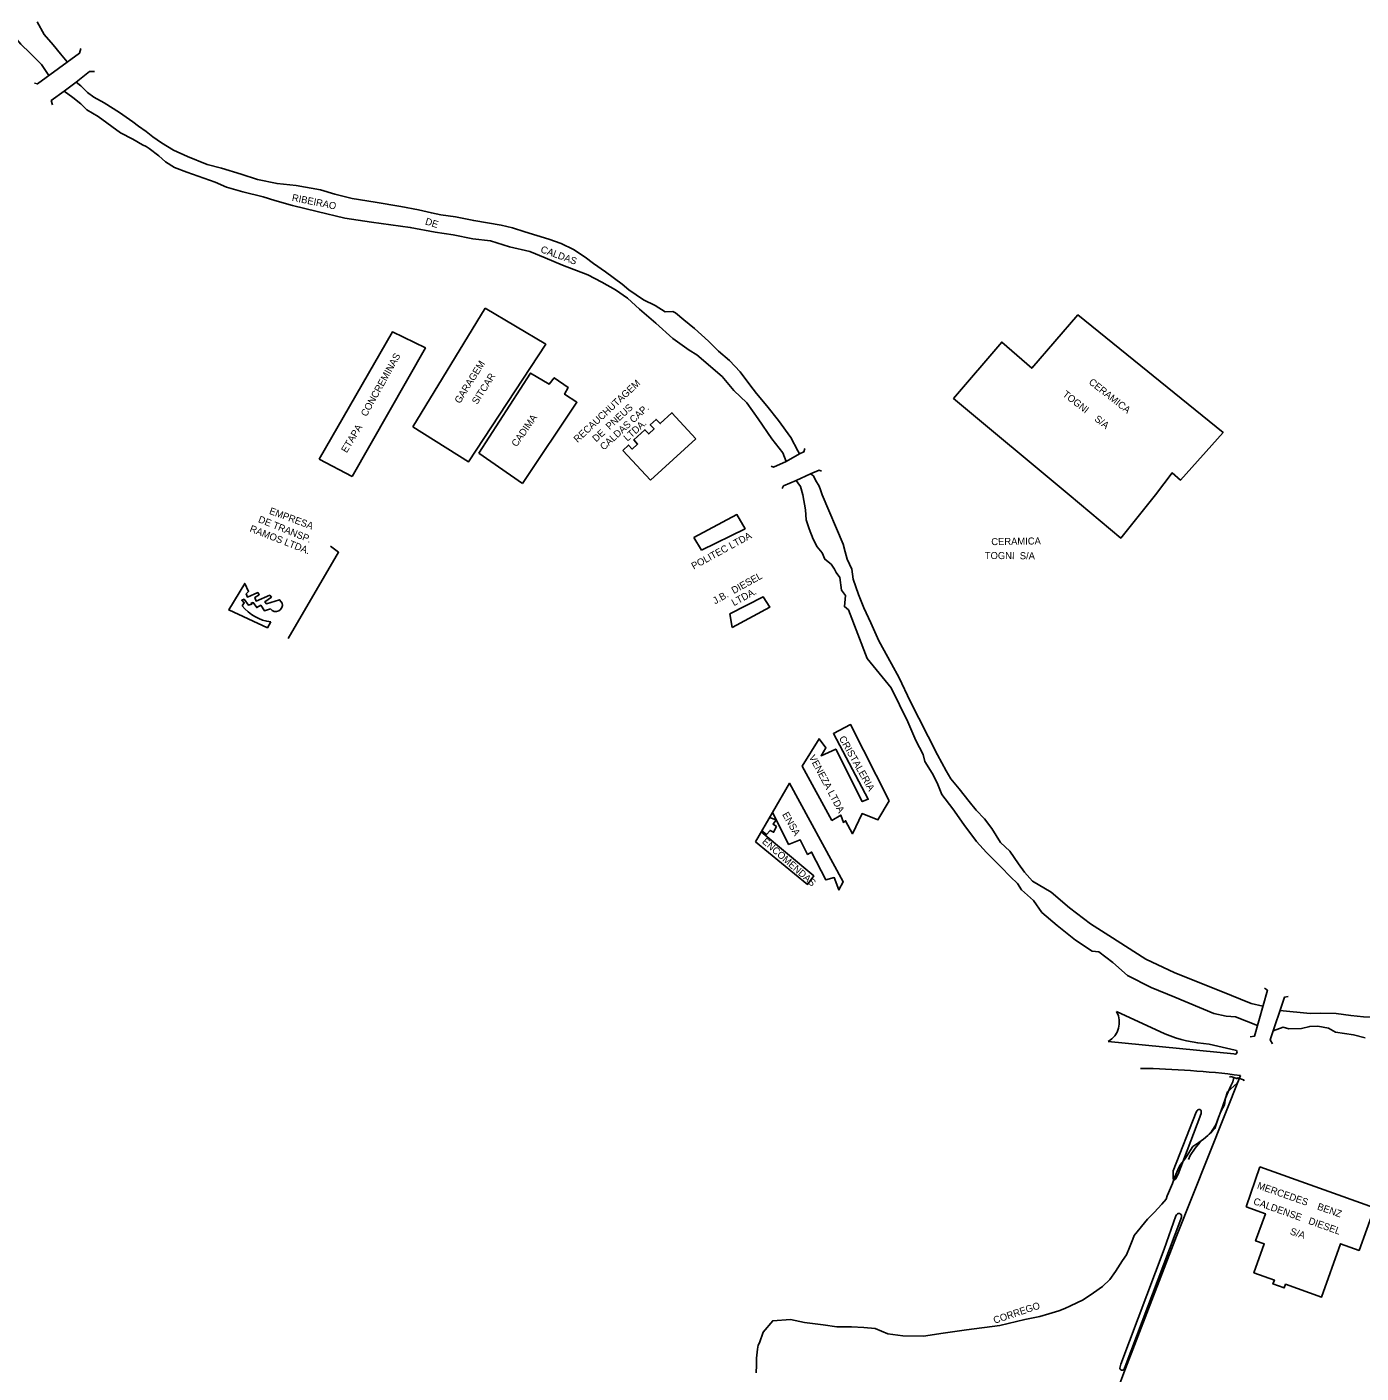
# Model space of a CAD drawing. Extents: x 325899 to 363134, y 7578590 to 7592502.
# Drawn here: x 334413 to 335173, y 7590002 to 7590768 of the extents above; entities that cross this region are included whole.
import ezdxf

# ---------------------------------------------------------------- set-up
doc = ezdxf.new("R2010")
doc.units = 0
for name, color, linetype in [('EDIFEXISTENT', 7, 'Continuous'), ('EDIFIDENTIF', 7, 'Continuous'), ('EDIFOBRAEXIS', 7, 'Continuous')]:
    doc.layers.add(name, color=color, linetype=linetype)

msp = doc.modelspace()

# ---------------------------------------------------------------- linework, layer by layer
at = {"layer": 'EDIFEXISTENT'}
for points in [[(334417.87, 7590736.5), (334419.49, 7590736.06), (334443.51, 7590753.51), (334444.25, 7590756.28)], [(334427.99, 7590724.19), (334427.33, 7590726.62), (334434.69, 7590731.93), (334441.52, 7590737.06), (334449.2, 7590743.16), (334451.89, 7590743.16)], [(334674.6, 7590608.27), (334709.05, 7590587.76), (334665.07, 7590520.77), (334633.23, 7590540.67)], [(334633.23, 7590540.67), (334674.6, 7590608.27)], [(335007.21, 7590501.91), (334941.33, 7590556.89), (334968.82, 7590588.94), (334985.9, 7590574.03), (335012.18, 7590604.43), (335094.84, 7590537.54), (335070.57, 7590510.36), (335065.86, 7590514.42), (335056.42, 7590501.91)], [(334580, 7590522.34), (334621.71, 7590594.78), (334640.48, 7590585.63), (334598.78, 7590512.32)], [(334670.91, 7590525.66), (334700.4, 7590571.33), (334710.89, 7590564.98), (334713.84, 7590568.61), (334721.87, 7590563.07), (334719.8, 7590559.24), (334726.75, 7590554.72), (334695.77, 7590508.37)], [(334752.89, 7590527.28), (334756.11, 7590530.35), (334758.25, 7590527.99), (334761.36, 7590530.84), (334759.18, 7590533.21), (334765.55, 7590539.01), (334767.7, 7590536.65), (334770.78, 7590539.51), (334768.56, 7590541.87), (334771.91, 7590544.94), (334774.21, 7590542.58), (334780.87, 7590548.74), (334794.45, 7590533.92)], [(334794.45, 7590533.92), (334768.78, 7590510.25)], [(334598.78, 7590512.32), (334580, 7590522.34)], [(334695.77, 7590508.37), (334670.91, 7590525.66)], [(334768.78, 7590510.25), (334752.89, 7590527.28)], [(334837.4, 7590518.24), (334838.82, 7590517.66), (334845.95, 7590520.88), (334853.59, 7590525.36), (334856.13, 7590526.47), (334856.66, 7590528.37)], [(334843.76, 7590505.48), (334844.52, 7590507.03), (334851.73, 7590510.12), (334859.87, 7590513.96), (334864.69, 7590516.07), (334866.19, 7590515.48)], [(335007.21, 7590501.91), (335036.61, 7590477.29), (335056.42, 7590501.91)], [(334793.37, 7590477.64), (334817.9, 7590490.76), (334822.54, 7590482.64), (334797.74, 7590470.52)], [(334797.74, 7590470.52), (334793.37, 7590477.64)], [(334813.94, 7590434.15), (334832.82, 7590443.95), (334836.66, 7590437.9), (334815.28, 7590426.44)], [(334815.28, 7590426.44), (334813.94, 7590434.15)], [(334872.02, 7590316.44), (334855.1, 7590347.46), (334864.73, 7590363.08), (334868.64, 7590357.81), (334865.88, 7590353.36), (334874.21, 7590357.11), (334889.33, 7590327.22), (334892.71, 7590328.61), (334872.86, 7590365.97), (334882.71, 7590371.12), (334904.65, 7590327.75)], [(334828.48, 7590304.36), (334847.84, 7590337.71), (334878.53, 7590281.63), (334876.02, 7590276.95), (334873.34, 7590284), (334868.67, 7590282.61), (334860.43, 7590298.51), (334858.16, 7590297.18), (334853.98, 7590305.41), (334847.39, 7590302.81), (334838.28, 7590321.24)], [(334904.65, 7590327.75), (334898.23, 7590316.79), (334889.24, 7590320.43), (334883.77, 7590308.89), (334879.82, 7590316.34), (334878.64, 7590315.35), (334877.09, 7590319.54), (334872.02, 7590316.44)], [(334836.54, 7590318.24), (334840.2, 7590316.84), (334838.52, 7590314.3), (334840.41, 7590313.05), (334838.86, 7590309.77), (334836.85, 7590310.79), (334834.76, 7590308.45), (334832.11, 7590310.61)], [(334831.81, 7590310.09), (334861.71, 7590284.89), (334858.22, 7590280.11), (334828.48, 7590304.36)], [(335118.44, 7590221), (335120.12, 7590219.77), (335112.81, 7590193.66), (335110.23, 7590193.19)], [(335131.94, 7590216.2), (335129.77, 7590215.81), (335121.67, 7590191.61), (335123.02, 7590189.29)], [(335098.52, 7590170.3), (335099.33, 7590170.68), (335102.72, 7590169.59), (335102.98, 7590169.08)], [(335102.38, 7590169.44), (335103.19, 7590169.83), (335106.57, 7590168.73), (335106.83, 7590168.23)], [(335066.46, 7590116.91), (335079.57, 7590150.35), (335079.9, 7590151.01), (335080.1, 7590151.39), (335080.48, 7590151.69), (335081.07, 7590151.89), (335081.65, 7590151.81), (335082.14, 7590151.53), (335082.42, 7590151.04), (335082.47, 7590150.28), (335082.31, 7590149.53), (335081.99, 7590148.58), (335081.58, 7590147.49), (335069.31, 7590115), (335068.17, 7590112.86), (335067.95, 7590112.43), (335067.72, 7590112.11), (335067.37, 7590111.79), (335067.19, 7590111.74), (335066.99, 7590111.76), (335066.66, 7590111.91), (335066.48, 7590112.17), (335066.4, 7590112.42), (335066.37, 7590112.78), (335066.46, 7590116.91)], [(335115.75, 7590119.18), (335181.05, 7590095.82), (335172.38, 7590071.59), (335161.85, 7590075.36), (335150.99, 7590045.02), (335130.47, 7590052.36), (335129.71, 7590050.24), (335123.3, 7590052.54), (335124.08, 7590054.72), (335112.44, 7590058.89), (335118.31, 7590075.28), (335113.43, 7590077.03), (335118.95, 7590092.45), (335107.98, 7590096.37)], [(335107.98, 7590096.37), (335115.75, 7590119.18)]]:
    msp.add_lwpolyline(points, dxfattribs=at)
at = {"layer": 'EDIFOBRAEXIS'}
for points in [[(334399.02, 7590772.12), (334401.6, 7590767.32), (334406.59, 7590762.65), (334409.99, 7590758.75), (334415.36, 7590753.62), (334421.71, 7590747.01), (334425.94, 7590740.73), (334425.94, 7590740.73)], [(334419.27, 7590771.33), (334423.33, 7590764.21), (334428.38, 7590758.22), (334432.51, 7590753.16), (334436.48, 7590748.58)], [(334441.52, 7590737.06), (334444.23, 7590734.93), (334448.06, 7590731.18), (334451.66, 7590728.47), (334457.44, 7590725.33), (334466.22, 7590719.8), (334473.79, 7590714.36), (334476.99, 7590711.97), (334481.39, 7590708.84)], [(334434.69, 7590731.93), (334439.69, 7590728.24), (334444.14, 7590724.68), (334447.67, 7590721.21), (334454.06, 7590717.51), (334466.73, 7590708.14), (334473.75, 7590704.49), (334479.23, 7590701.32), (334481.39, 7590700.4)], [(334481.39, 7590708.84), (334485.11, 7590705.88), (334490.11, 7590702.43), (334497.03, 7590698.34), (334504.86, 7590694.7), (334516.22, 7590690.03), (334524.23, 7590688.09), (334535.54, 7590684.56), (334544.82, 7590681.51), (334555.95, 7590679.21), (334566.78, 7590678.19), (334580.68, 7590675.64), (334588.97, 7590673.28), (334598.81, 7590670.78), (334611.8, 7590668.67), (334626.43, 7590666.22), (334636.47, 7590664.33), (334643.85, 7590662.58), (334649.35, 7590661.51), (334657.7, 7590660.23), (334667.99, 7590658.19), (334683.72, 7590655.49), (334690.13, 7590654.01), (334697.03, 7590651.68), (334710.85, 7590647.55), (334717.72, 7590645.04), (334724.87, 7590641.71), (334731.41, 7590637.39), (334736.28, 7590633.76), (334743.04, 7590629.04), (334752.52, 7590621.88), (334756.38, 7590618.8), (334764.79, 7590612.99), (334771.33, 7590609.74), (334777.01, 7590606.13), (334781.37, 7590606.41), (334782.92, 7590605.72), (334787.61, 7590601.71), (334793.69, 7590596.78), (334801.73, 7590589.5), (334807.43, 7590583.71), (334813.76, 7590578.43), (334819.8, 7590572.11), (334825.37, 7590564.57), (334829.12, 7590559.62), (334835.02, 7590552.61), (334841.66, 7590544.29), (334848.7, 7590534.54), (334852.55, 7590527.01), (334853.59, 7590525.36)], [(334481.39, 7590700.4), (334483.04, 7590699.18), (334488.62, 7590694.96), (334492.43, 7590691.72), (334497.6, 7590688.34), (334504.57, 7590685.83), (334520.7, 7590680.06), (334527.17, 7590677.23), (334536.42, 7590674.59), (334548.01, 7590671.74), (334554.75, 7590669.63), (334564.77, 7590666.83), (334578.84, 7590663.39), (334594.62, 7590659.55), (334609.78, 7590657.3), (334631.87, 7590654.24), (334645.95, 7590651.64), (334656.37, 7590650.04), (334667.5, 7590647.87), (334677.47, 7590646.72), (334688.37, 7590643.21), (334699.99, 7590640.56), (334708.66, 7590636.98), (334718.62, 7590632.74), (334732.92, 7590627.25), (334740.98, 7590623.03), (334748.74, 7590618.71), (334755.61, 7590613.99), (334762.45, 7590607.79), (334771.68, 7590599.72), (334781.51, 7590591.09), (334790.64, 7590584.43), (334795.12, 7590581.79), (334809.55, 7590569.33), (334816.18, 7590561.36), (334823.64, 7590554.4), (334830.04, 7590545.16), (334837.9, 7590533.79), (334844.13, 7590525.98), (334845.95, 7590520.88)], [(334859.87, 7590513.96), (334861.47, 7590512.82), (334862.94, 7590509.98), (334864.56, 7590507.32), (334865.27, 7590505.46), (334866.58, 7590501.91)], [(334851.73, 7590510.12), (334852.71, 7590508.77), (334854.07, 7590506.63), (334855.52, 7590501.91)], [(335114.51, 7590199.74), (335101.9, 7590204.73), (335096.55, 7590205.08), (335089.53, 7590206.58), (335067.46, 7590215.91), (335053.97, 7590221.32), (335040.5, 7590228.27), (335032.02, 7590235.61), (335024.08, 7590241.72), (335020.33, 7590242.02), (335010.79, 7590248.34), (335000.42, 7590256.71), (334991.71, 7590264.15), (334986.83, 7590270.98), (334980.1, 7590276.94), (334977.78, 7590280.58), (334973.72, 7590284.3), (334968.24, 7590290.01), (334960.06, 7590298.32), (334954.39, 7590304.56), (334947.14, 7590314.24), (334940.9, 7590323.14), (334934.67, 7590331.29), (334931.94, 7590337.93), (334929.06, 7590343.46), (334925.02, 7590350.09), (334924.11, 7590354.09), (334919.83, 7590362.09), (334915.27, 7590372.75), (334905.73, 7590392.01), (334892.13, 7590408.7), (334881.4, 7590436.44), (334879.14, 7590438.36), (334879.76, 7590444.54), (334877.43, 7590447.58), (334876.62, 7590454.85), (334874.52, 7590457.72), (334873.5, 7590459.72), (334871.63, 7590462.46), (334867.99, 7590465.25), (334866.42, 7590468.89), (334863.64, 7590472.34), (334861.43, 7590476.63), (334859.01, 7590482.52), (334857.46, 7590487.78), (334857.02, 7590493.5), (334855.52, 7590501.91)], [(334866.58, 7590501.91), (334878.4, 7590473.83), (334879.54, 7590469.56), (334880.71, 7590465.28), (334883.38, 7590459.63), (334884.2, 7590453.91), (334887.14, 7590445.14), (334890.18, 7590437.69), (334894.21, 7590429.15), (334898.74, 7590418.9), (334906.04, 7590405.77), (334910.32, 7590397.74), (334916.67, 7590384.36), (334921.54, 7590374.77), (334932.11, 7590353.81), (334937.04, 7590344.7), (334939.75, 7590340.18), (334944.6, 7590334.57), (334950.17, 7590327.21), (334954.15, 7590322.45), (334958.99, 7590317.51), (334963.08, 7590311.92), (334968.1, 7590303.87), (334973.35, 7590299.06), (334978.36, 7590291.88), (334981.68, 7590287.01), (334986.4, 7590281.85), (334996.86, 7590275.56), (335007.35, 7590266.71), (335019.31, 7590257.57), (335029.77, 7590250.9), (335050.8, 7590237.51), (335067.37, 7590229.76), (335093.65, 7590219.22), (335110.94, 7590212.21), (335117.61, 7590210.8)], [(334586.32, 7590472.67), (334591.01, 7590469.28), (334562.22, 7590420.07)], [(334552.46, 7590429.55), (334550.43, 7590426.27), (334528.41, 7590436.38), (334537.53, 7590451.49), (334539.76, 7590446.94), (334538.4, 7590445.54), (334539.1, 7590443.69), (334545.01, 7590446.27), (334545.8, 7590445.03), (334543.23, 7590443.44), (334543.98, 7590441.47), (334551.76, 7590444.76), (334552.78, 7590443.68), (334549.07, 7590441.1), (334550.02, 7590439.86), (334557.4, 7590442.22), (334558.85, 7590440.25)], [(334552.24, 7590437.02), (334548.88, 7590435.88), (334546.63, 7590439.06), (334544.36, 7590437.7), (334542.36, 7590440.63), (334541.3, 7590440.34), (334541.53, 7590439.68), (334539.64, 7590439.16), (334537.21, 7590442.49), (334535.82, 7590441.9), (334537.32, 7590440.39), (334536.04, 7590438.79)], [(335034.25, 7590207.61), (335061.74, 7590195)], [(335127.24, 7590208.26), (335144.39, 7590206.53), (335150.16, 7590206.82), (335159.36, 7590206.58), (335167.65, 7590205.44), (335174.8, 7590204.62), (335180.88, 7590204.46), (335185.95, 7590203.35), (335196.77, 7590203.09), (335199.54, 7590203.47), (335202.54, 7590203.18), (335212.7, 7590200.21), (335216.52, 7590199.9), (335229.19, 7590198.82), (335236.87, 7590198.04), (335241.05, 7590198.06), (335246.57, 7590198.38), (335262.75, 7590196.5), (335270.48, 7590195.36), (335273.49, 7590195.64), (335281.39, 7590195.43)], [(335123.34, 7590196.62), (335129.17, 7590198.73), (335132.26, 7590197.86), (335139.58, 7590198.04), (335144.29, 7590199.16), (335148.79, 7590199.36), (335154.98, 7590198.16), (335158.82, 7590195.86), (335169.14, 7590194.38), (335175.79, 7590192.67)], [(335101.02, 7590183.58), (335029.42, 7590190.59)], [(335086.93, 7590189.11), (335101.85, 7590185.69)], [(335103.98, 7590169.57), (335103.58, 7590168.41), (335102.95, 7590166.85), (335097.42, 7590161.86), (335096.25, 7590158.3), (335095.67, 7590154.48), (335093.56, 7590150.66), (335092.21, 7590147.24), (335090.16, 7590141), (335088.55, 7590139.24), (335087.04, 7590137.83), (335083.67, 7590134.96), (335081.02, 7590133.04), (335077.71, 7590130.76), (335074.06, 7590125.14), (335072.88, 7590123.48), (335070.28, 7590119.98), (335069.03, 7590117.41), (335067.4, 7590113.49), (335066.06, 7590109.67), (335063.8, 7590104.44), (335063, 7590102.61), (335062.53, 7590100.7), (335059.93, 7590097.99), (335055.67, 7590093.21), (335051.91, 7590089.47), (335044.2, 7590080.07), (335043.5, 7590078.01), (335041.47, 7590073.19), (335039.8, 7590069.06), (335037.61, 7590065.77), (335033.66, 7590059.62), (335030.29, 7590055), (335026.1, 7590051.03), (335021.11, 7590047.42), (335015.22, 7590043.52), (335008, 7590040.04), (335004.81, 7590038.59), (335001.36, 7590037.27), (334995.68, 7590035.53), (334990.41, 7590034), (334981.91, 7590032.24), (334967.67, 7590028.84), (334948.63, 7590026.33), (334935.46, 7590024.39), (334924.19, 7590022.79), (334912.5, 7590022.94), (334903.93, 7590024.05), (334896.59, 7590027.2), (334890.31, 7590027.67), (334883.22, 7590028), (334874.83, 7590028.02), (334867.02, 7590029.16), (334856.44, 7590030.54), (334848.4, 7590032.34), (334838.35, 7590031.59), (334832.88, 7590025.05), (334830.78, 7590019.04), (334830.05, 7590017.69), (334829.56, 7590015.32), (334829.11, 7590010.14), (334829.05, 7590006.29), (334828.88, 7590001.91)], [(335104.74, 7590171.25), (335068.36, 7590079.66), (335038.4, 7590001.91)], [(335101.02, 7590170.09), (335100.45, 7590167.67), (335099.24, 7590165.32), (335097.75, 7590162.02), (335096.25, 7590158.3), (335094.97, 7590154.46), (335093.56, 7590150.66), (335092.21, 7590147.24), (335090.68, 7590143.17), (335088.24, 7590139.38), (335086.12, 7590137.04), (335083.67, 7590134.96), (335081.68, 7590133.03), (335078.9, 7590129.9), (335076.19, 7590125.62), (335075.26, 7590123.48)], [(335061.37, 7590072.32), (335068.01, 7590091.23), (335068.39, 7590091.87), (335068.83, 7590092.42), (335069.3, 7590092.62), (335069.82, 7590092.66), (335070.31, 7590092.56), (335070.63, 7590092.34), (335070.92, 7590091.97), (335071.1, 7590091.54), (335071.2, 7590091.03), (335071.16, 7590090.46), (335070.73, 7590089.31), (335039.07, 7590005.55), (335038.78, 7590004.8), (335038.63, 7590004.45)], [(335038.63, 7590004.45), (335038.26, 7590003.74), (335038, 7590003.44), (335037.76, 7590003.36), (335037.37, 7590003.38), (335037.04, 7590003.47), (335036.72, 7590003.59), (335036.48, 7590003.75), (335036.27, 7590003.98), (335036.11, 7590004.3), (335036.04, 7590004.57), (335036.18, 7590005.23), (335036.68, 7590006.86), (335061.37, 7590072.32)], [(335038.4, 7590001.91), (334997.72, 7589892.76), (334997.75, 7589892.73)]]:
    msp.add_lwpolyline(points, dxfattribs=at)
for centre, radius, start, end in [((334555.81, 7590454.71), 25.38, 218.84776, 262.42385), ((334555.25, 7590439.23), 3.74, 216.35819, 15.75138), ((335023.19, 7590201.55), 12.61, 299.60755, 28.72583), ((335091.92, 7590267.24), 78.29, 247.32879, 266.34783), ((335101.7, 7590184.53), 1.17, 234.47922, 82.89846), ((335039.42, 7589653), 522.36, 82.81674, 89.07327)]:
    msp.add_arc(centre, radius, start, end, dxfattribs=at)

# ---------------------------------------------------------------- texts
at = {"layer": 'EDIFIDENTIF'}
for s, rotation, p in [('RIBEIRAO', 348.64108, (334564.18, 7590669.47)), ('DE', 342.53304, (334640.02, 7590656.08)), ('CALDAS', 340.09914, (334705.74, 7590640.22)), ('CONCREMINAS', 60.85843, (334606.89, 7590546.21)), ('GARAGEM', 58.05315, (334660.14, 7590553.63)), ('SITCAR', 57.36928, (334669.97, 7590553.16)), ('RECAUCHUTAGEM', 42.92646, (334727.13, 7590531.45)), ('CERAMICA', 321.90479, (335018.01, 7590565.49)), ('TOGNI    S/A', 322.28349, (335003.11, 7590558.51)), ('DE  PNEUS', 42.46001, (334737.75, 7590531.76)), ('CALDAS CAP.', 42.54646, (334742.14, 7590527.12)), ('CADIMA', 54.96919, (334692.41, 7590528.97)), ('ETAPA', 58.77996, (334595.61, 7590525.56)), ('LTDA.', 41.83225, (334755.52, 7590532.18)), ('EMPRESA', 339.71222, (334551.15, 7590491.22)), ('RAMOS LTDA.', 338.68254, (334540.04, 7590481.18)), ('DE TRANSP.', 338.09647, (334544.87, 7590486.51)), ('POLITEC LTDA', 28.58027, (334793.3, 7590459.31)), ('CERAMICA', 0.92847, (334962.86, 7590473.3)), ('TOGNI  S/A', 359.62409, (334959.15, 7590465.43)), ('J.B.  DIESEL', 28.9383, (334805.5, 7590439.52)), ('LTDA.', 28.38985, (334816.2, 7590438.5)), ('CRISTALERIA', 299.53875, (334875.89, 7590363.3)), ('VENEZA LTDA', 297.91116, (334858.83, 7590352.64)), ('ENSA', 299.60395, (334843.6, 7590319.95)), ('ENCOMENDAS', 318.67875, (334831.94, 7590303.96)), ('MERCEDES    BENZ', 340.71486, (335113.94, 7590106.97)), ('CALDENSE   DIESEL', 340.3761, (335111.76, 7590098.03)), ('S/A', 341.50395, (335132.68, 7590080.83)), ('CORREGO', 18.53793, (334964.78, 7590029.79))]:
    msp.add_text(s, height=4, rotation=rotation, dxfattribs=at).set_placement(p)

doc.saveas('drawing.dxf')
